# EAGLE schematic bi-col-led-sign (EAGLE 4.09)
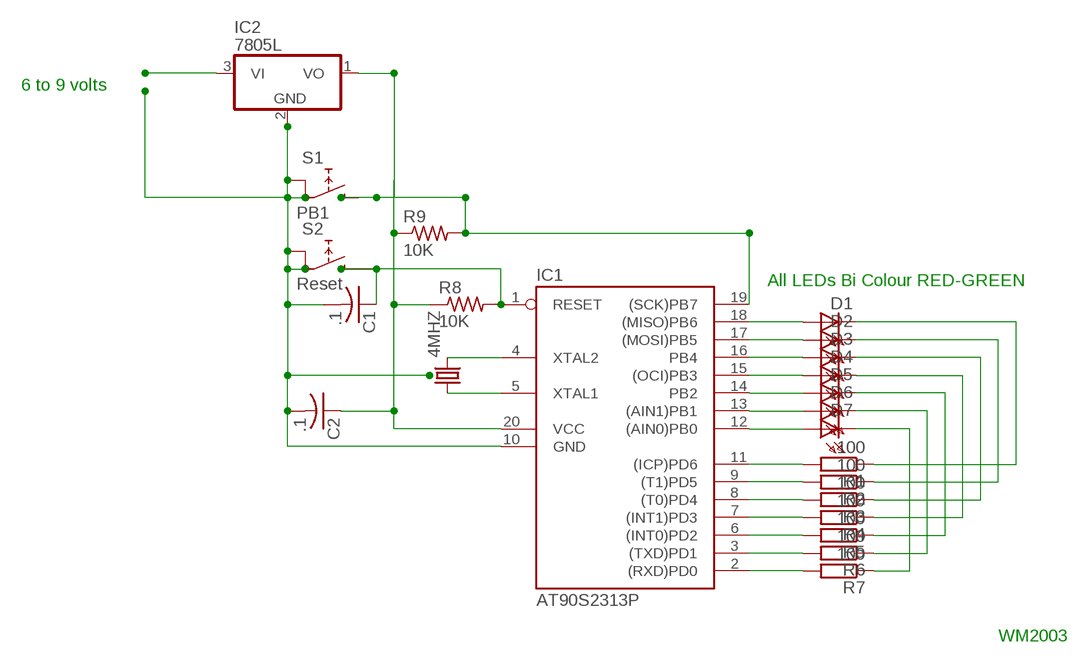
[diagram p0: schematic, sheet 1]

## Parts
4MHZ  CRYTALHC18U-V  [HC18U-V]
C1  .1  C-US025-040X050  [C025-040X050]
C2  .1  C-US050-035X075  [C050-035X075]
D1  LED5MM  [LED5MM]
D2  LED5MM  [LED5MM]
D3  LED5MM  [LED5MM]
D4  LED5MM  [LED5MM]
D5  LED5MM  [LED5MM]
D6  LED5MM  [LED5MM]
D7  LED5MM  [LED5MM]
IC1  AT90S2313P  [DIL20]
IC2  7805L  [TO92]
R1  100  R-EU_0204/7  [0204/7]
R2  100  R-EU_0204/7  [0204/7]
R3  100  R-EU_0204/7  [0204/7]
R4  100  R-EU_0204/7  [0204/7]
R5  100  R-EU_0204/7  [0204/7]
R6  100  R-EU_0204/7  [0204/7]
R7  100  R-EU_0204/7  [0204/7]
R8  10K  R-US_0207/15  [0207/15]
R9  10K  R-US_0207/15  [0207/15]
S1  PB1  RDT1034  [RDT1034]
S2  Reset  RDT1034  [RDT1034]

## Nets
N$1: IC1.2((RXD)PD0) R7.2
N$2: IC1.3((TXD)PD1) R6.2
N$3: IC1.6((INT0)PD2) R5.2
N$4: IC1.7((INT1)PD3) R4.2
N$5: IC1.8((T0)PD4) R3.2
N$6: IC1.9((T1)PD5) R2.2
N$7: IC1.11((ICP)PD6) R1.2
N$8: D6.A IC1.13((AIN1)PB1)
N$9: D7.A IC1.12((AIN0)PB0)
N$10: D5.A IC1.14(PB2)
N$11: D4.A IC1.15((OCI)PB3)
N$12: D3.A IC1.16(PB4)
N$13: D2.A IC1.17((MOSI)PB5)
N$14: D1.A IC1.18((MISO)PB6)
N$15: D7.K(C) R7.1
N$16: D6.K(C) R6.1
N$17: 4MHZ.2 IC1.4(XTAL2)
N$18: C2.1 IC1.20(VCC) R8.1 R9.1
N$19: D5.K(C) R5.1
N$20: D4.K(C) R4.1
N$21: D3.K(C) R3.1
N$22: D2.K(C) R2.1
N$23: D1.K(C) R1.1
N$24: 4MHZ.1 IC1.5(XTAL1)
N$25: C1.2 C2.2 IC1.10(GND) IC2.2(GND) S1.A S1.A1 S2.A S2.A1
N$26: IC1.19((SCK)PB7) IC2.1(VO) R9.2 S1.B
N$27: C1.1 IC1.1(RESET) R8.2 S2.B
N$29: IC2.3(VI)

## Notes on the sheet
- 6 to 9 volts
- All LEDs Bi Colour RED-GREEN
- WM2003

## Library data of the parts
4MHZ = crystal:CRYTAL: CRYSTAL
C1 C2 = rcl:C-US: CAPACITOR, American symbol
D1-D7 = led:LED5MM: LED
IC1 = atmel:AT90S2313: MICROCONTROLLER 2 Kbytes FLASH 128 bytes SRAM 128 bytes EEPROM UART
IC2 = linear:78*: Positive VOLTAGE REGULATOR
R1-R7 = rcl:R-EU_: RESISTOR, European symbol
R8 R9 = rcl:R-US_: RESISTOR, American symbol
S1 S2 = switch:RDT1034: PUSH SWITCH www.radiohm.com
